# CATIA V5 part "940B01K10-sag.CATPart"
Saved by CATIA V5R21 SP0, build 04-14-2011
Part number: 940B01K10-sag
Bounding box of the stored display mesh (mm): x -49.351 to 77.949, y -15.698 to 19.302, z -6.85 to 7.15
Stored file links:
  C:\Users\ALI OZGUN\Desktop\alhan\940B01K10-sag.CATPart
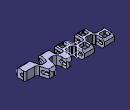
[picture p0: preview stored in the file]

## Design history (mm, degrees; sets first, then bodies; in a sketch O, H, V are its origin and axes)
Set1 "CURVE"
  DatumCurve1 to DatumCurve105
  Plane1: stored without definition
Set2 "SURFACE"
  Plane2: type 1Curve, Element1 DatumCurve19
  Sketch1 on Plane2, origin (0, 0, -3.1959), H (1, 0, 0), V (0, -1, 0)
    line L1 (49.4472, 15.9983) -> (32.7694, 15.9983)
    line L2 (48.5473, -19.0017) -> (65.7661, -19.0017)
    line L3 (-61.2339, -0.5841) -> (-61.2339, 15.0809)
    line L4 (65.7661, -19.0017) -> (65.7661, 3.0782)
    point P1 (65.7661, -19.0017)
    line L5 (49.4472, 15.9983) -> (49.0081, 3.1001)
    line L6 (49.0081, 3.1001) -> (53.2715, -2.5577)
    line L7 (53.2715, -2.5577) -> (61.843, -2.5577)
    point P2 (49.0081, 3.1001)
    point P3 (53.2715, -2.5577)
    point P4 (49.4472, 15.9983)
    line L8 (61.843, -2.5577) -> (65.7661, 3.0782)
    point P5 (61.843, -2.5577)
    point P6 (65.7661, 3.0782)
    reference intersected line E1 through (0, 0) direction (0, 1) from yz-plane
    reference intersected line E2 through (0, 0) direction (0, 1) from yz-plane
    construction line L9 (41.1083, 0) -> (41.1083, 12.9106)
    construction line L10 (41.1083, 12.9106) -> (46.3559, 12.9106)
    construction line L11 (46.3559, 12.9106) -> (46.3559, 3.0133)
    construction line L12 (46.3559, 3.0133) -> (41.1083, 3.0133)
    point P7 (46.3559, 12.9106)
    point P8 (46.3559, 3.0133)
    point P9 (41.1083, 12.9106)
    point P10 (41.1083, 3.0133)
    line L13 (41.1083, 0) -> (50.5276, 0)
    line L14 (48.5473, -19.0017) -> (50.5276, 0)
    point P11 (50.5276, 0)
    point P12 (41.1083, 0)
    point P13 (48.5473, -19.0017)
    point P14 (35.8607, 12.9106)
    point P15 (41.1083, 12.9106)
    construction line L15 (41.1083, 12.9106) -> (35.8607, 12.9106)
    point P16 (35.8607, 3.0133)
    construction line L16 (35.8607, 12.9106) -> (35.8607, 3.0133)
    point P17 (41.1083, 3.0133)
    construction line L17 (35.8607, 3.0133) -> (41.1083, 3.0133)
    point P18 (31.6891, 0)
    point P19 (41.1083, 0)
    line L18 (41.1083, 0) -> (31.6891, 0)
    point P20 (33.6694, -19.0017)
    line L19 (33.6694, -19.0017) -> (31.6891, 0)
    point P21 (16.4506, -19.0017)
    line L20 (33.6694, -19.0017) -> (16.4506, -19.0017)
    point P22 (16.4506, 3.0782)
    line L21 (16.4506, -19.0017) -> (16.4506, 0)
    point P23 (20.3736, -2.5577)
    line L22 (20.3736, -2.5577) -> (16.5464, 2.9405)
    point P24 (28.9451, -2.5577)
    line L23 (28.9451, -2.5577) -> (20.3736, -2.5577)
    point P25 (33.2086, 3.1001)
    line L24 (33.2086, 3.1001) -> (28.9451, -2.5577)
    point P26 (32.7694, 15.9983)
    line L25 (32.7694, 15.9983) -> (33.2086, 3.1001)
    axis line L26 (24.8802, -15.8106) -> (24.8802, 20.8842)
    line L27 (16.991, 15.9983) -> (16.5464, 2.9405)
    point P29 (13.8998, 3.0133)
    point P30 (13.8998, 12.9106)
    construction line L28 (13.8998, 12.9106) -> (13.8998, 3.0133)
    point P31 (8.6521, 0)
    line L29 (8.6521, 0) -> (16.4506, 0)
    point P32 (8.6521, 0)
    line L30 (8.6521, 0) -> (-0.2618, 0)
    point P33 (3.4045, 3.0133)
    point P34 (3.4045, 12.9106)
    construction line L31 (3.4045, 12.9106) -> (3.4045, 3.0133)
    point P35 (8.6521, 3.0133)
    construction line L32 (3.4045, 3.0133) -> (8.6521, 3.0133)
    point P36 (8.6521, 3.0133)
    construction line L33 (13.8998, 3.0133) -> (8.6521, 3.0133)
    point P37 (8.6521, 12.9106)
    construction line L34 (8.6521, 12.9106) -> (3.4045, 12.9106)
    point P38 (8.6521, 12.9106)
    construction line L35 (8.6521, 12.9106) -> (13.8998, 12.9106)
    point P39 (0.3133, 15.9983)
    line L36 (0.3133, 15.9983) -> (0.7524, 3.1001)
    line L37 (0.7524, 3.1001) -> (-3.8134, -2.9589)
    line L38 (16.991, 15.9983) -> (0.3133, 15.9983)
    line L39 (-0.2618, 0) -> (0.5916, -19.0017)
    line L40 (-12.1477, -5.1469) -> (-12.4932, -19.0017)
    line L41 (-3.8134, -2.9589) -> (-12.4906, -2.9589)
    line L42 (-12.4906, -2.9589) -> (-12.6654, 12.1222)
    line L43 (-29.6656, -3.0126) -> (-25.0164, 15.9983)
    line L44 (-39.0662, -3.1542) -> (-29.6656, -3.0126)
    line L45 (-44.327, 15.3928) -> (-39.0662, -3.1542)
    line L46 (-43.9186, 0.391) -> (-38.7475, -19.0017)
    line L47 (-43.9186, 0.391) -> (-61.2339, -0.5841)
    line L48 (-61.2339, 15.0809) -> (-44.327, 15.3928)
    line L49 (-16.4275, 15.9983) -> (-25.0164, 15.9983)
    line L50 (-16.4275, 15.9983) -> (-12.6654, 12.1222)
    line L51 (-24.9197, 0.2086) -> (-29.3974, -19.0017)
    line L52 (-24.9197, 0.2086) -> (-16.3942, 0.2086)
    line L53 (-16.3942, 0.2086) -> (-12.1477, -5.1469)
    line L54 (-29.3974, -19.0017) -> (-38.7475, -19.0017)
    line L55 (0.5916, -19.0017) -> (-12.4932, -19.0017)
    distance L2 L1 = 35
    distance L3 L4 = 127
    angle E1 L5 = 1.95
    angle E2 L6 = 37
    horizontal: L1 H, L2 H, L7 H, L10 H, L12 H, L13 H, L38 H, L41 H, L49 H, L52 H
    fix: L1, L9
    vertical: L3 V, L4 V, L9 V, L11 V, L26 V
    coincidence: P10 L9, L1 L38, P22 L22, P22 L21, L38 L49, L20 L54, L20 L55
    symmetry: P7 P14 L9, P9 P15 L9, L10 L15 L9, P8 P16 L9, L11 L16 L9, P10 P17 L9, L12 L17 L9, P11 P18 L9, P12 P19 L9, L13 L18 L9, P13 P20 L9, L14 L19 L9, P1 P21 L9, L2 L20 L9, P6 P22 L9, L4 L21 L9, P5 P23 L9, L8 L22 L9, P3 P24 L9, L7 L23 L9, P2 P25 L9, L6 L24 L9, P4 P26 L9, L5 L25 L9, L25 L27 L26, P16 P29 L26, P14 P30 L26, L16 L28 L26, P19 P31 L26, L18 L29 L26, P12 P32 L26, L13 L30 L26, P8 P33 L26, P7 P34 L26, L11 L31 L26, P10 P35 L26, L12 L32 L26, P17 P36 L26, L17 L33 L26, P9 P37 L26, L10 L34 L26, P15 P38 L26, L15 L35 L26, P4 P39 L26, L5 L36 L26, L6 L37 L26
  Sweep1: type Segment, GuideCrv Sketch1, Length1 4, Length2 5, Angle -1, DraftDirection (0, 0, 1)
  Sketch2 on yz-plane, origin (0, 0, 0), H (0, 1, 0), V (0, 0, 1)
    line L1 (-24.9191, -6.9968) -> (50.389, -6.9968)
    horizontal: L1 H
  Extrude1: Element1 Sketch2, Lim1 80, Lim2 80
  Trim1: Trimmed (Sweep1; Extrude1)
  Sketch3 on yz-plane, origin (0, 0, 0), H (0, 1, 0), V (0, 0, 1)
    line L1 (-48.3055, 0) -> (52.6647, 0)
    horizontal: L1 H
    coincidence: O L1
  Extrude2: Element1 Sketch3, Lim1 80, Lim2 80
  Trim2: Trimmed (Trim1; Extrude2)
  Extrude3: Element1 Sketch7, Lim1 10, Lim2 10
  Translate1: ToTransfor Extrude3, Direction (1, 0, 0), Length 32.6
  Extrude4: Element1 Sketch8, Lim1 10, Lim2 10
  Translate2: ToTransfor Extrude4, Direction (1, 0, 0), Length 32.8
  Sweep2: type Segment, GuideCrv Sketch11, Length1 10, Length2 5, Angle -1, DraftDirection (0, 0, 1)
  Translate3: ToTransfor Sweep2, Direction (1, 0, 0), Length -32.8
  Sketch4 on face of CloseSurface1, origin (0, 0, 0), H (1, 0, 0), V (0, 1, 0)
    line L1 (-3.8486, 19.8441) -> (1.0015, 13.5162)
  Sweep3: type Segment, GuideCrv Sketch4, Length1 10, Length2 5, Angle 1, DraftDirection (0, 0, 1)
  Plane3: type 1Curve, Element1 DatumCurve99
  Sketch5 on Plane3, origin (0, 0, -5.2979), H (1, 0, 0), V (0, -1, 0)
    line L1 (-37.6706, -7.3878) -> (-35.3775, -14.835)
    line L2 (-32.6098, -14.835) -> (-30.9175, -7.3878)
    offset line E2 (-36.4878, -14.835) -> (-31.7318, -14.835) from edge [face of Mirror1 | face of CloseSurface1]
    offset line E3 (-35.3775, -14.835) -> (-32.6098, -14.835) from edge [face of Mirror1 | face of CloseSurface1]
    line L3 (-37.6706, -7.3878) -> (-30.9175, -7.3878)
    point P5 (-36.4878, -7.3878)
    point P6 (-31.7318, -7.3878)
    construction line L4 (-36.4878, -14.835) -> (-36.4878, -7.3878)
    construction line L5 (-31.7318, -14.835) -> (-31.7318, -7.3878)
    distance E2 L3 = 7.4472
    perpendicularity: L4 E2, L4 L3, L5 E2, L5 L3
    coincidence: P5 L3, P6 L3
  Sweep4: type Segment, GuideCrv Sketch5, Length1 5, Length2 5, Angle -1, DraftDirection (0, 0, 1)
  Sketch6 on yz-plane, origin (0, 0, 0), H (0, 1, 0), V (0, 0, 1)
    line L1 (-47.946, -0.4507) -> (26.6531, -0.4507)
    horizontal: L1 H
  Extrude5: Element1 Sketch6, Lim1 100, Lim2 100
  Trim3: Trimmed (Sweep4; Extrude5)
  Sweep5: type Segment, GuideCrv Sketch12, Length1 5, Length2 5, Angle -1, DraftDirection (0, 0, 1)
  Trim4: Trimmed (Extrude5; Sweep5)
  MultiExtract1: ListOfMultiExtractConstraints (MultiExtractConstraint face of Split9; MultiExtractConstraint face of Fillet45; MultiExtractConstraint face of Split9; MultiExtractConstraint face of Fillet47; MultiExtractConstraint face of Split9; MultiExtractConstraint face of Split9; MultiExtractConstraint face of Fillet49; MultiExtractConstraint face of Fillet48; MultiExtractConstraint face of Fillet46; MultiExtractConstraint face of Split9)
  Extrapol1: ToExtrapol edge of MultiExtract1, Support MultiExtract1, Length 10
  Extrapol2: ToExtrapol edge [end face of Pocket4 | face of Pocket5 from Sketch15.E2], Support face of Pocket5 from Sketch15.E2, Length 10
  Trim5: Trimmed (Extrapol1; Extrapol2)
  Extrapol3: ToExtrapol edge of MultiExtract1, Support Trim5, Length 1
  Extrapol4: ToExtrapol edge [face of Pocket4 from Sketch14.L2 | face of CloseSurface1], Support face of Pocket4 from Sketch14.L2, Length 5
  Extrapol5: ToExtrapol edge [face of Pocket4 from Sketch14.L1 | face of Mirror1], Support face of Pocket4 from Sketch14.L1, Length 5
  Extrapol6: ToExtrapol edge [face of Mirror1 | face of Pocket4 from Sketch14.L4], Support face of Pocket4 from Sketch14.L4, Length 5
  Trim6: Trimmed (Extrapol6; Extrapol5; Extrapol4)
  Extrapol7: ToExtrapol edge [face of CloseSurface1 | face of Split10], Support face of Split10, Length 5
  Trim7: Trimmed (Extrapol7; Trim6)
  Extrapol8: ToExtrapol edge [face of CloseSurface1 | face of Pocket4 from Sketch14.L3], Support face of Pocket4 from Sketch14.L3, Length 5
  Trim8: Trimmed (Extrapol8; Trim7)
Set3
  CLDGeom1 "4_1.1"
  Plane4: type Offset, RefPlane yz-plane, Offset -63
Body1 (main body)
  CloseSurface1: CloseElement Trim2
  Sketch7 on face of CloseSurface1, origin (0, 0, -6.9968), H (1, 0, 0), V (0, -1, 0)
    line L1 (3.5232, 12.867) -> (13.7904, 12.867)
    line L2 (13.7904, 12.867) -> (13.7904, 3.1238)
    line L3 (13.7904, 3.1238) -> (3.5232, 3.1238)
    line L4 (3.5232, 3.1238) -> (3.5232, 12.867)
    horizontal: L1 H, L3 H
    vertical: L2 V, L4 V
    fix: L4, L1
  Split1: SplitPlane Extrude3
  Split2: SplitPlane Translate1
  Sketch8 on face of CloseSurface1, origin (0, 0, -6.9968), H (1, 0, 0), V (0, -1, 0)
    line L1 (19.6709, -6.2611) -> (30.062, -6.2611)
    line L2 (30.062, -6.2611) -> (30.062, -15.6449)
    line L3 (30.062, -15.6449) -> (19.6709, -15.6449)
    line L4 (19.6709, -15.6449) -> (19.6709, -6.2611)
    horizontal: L1 H, L3 H
    vertical: L2 V, L4 V
    fix: L1, L4, L2
  Split3: SplitPlane Translate2
  Split4: SplitPlane Extrude4
  Sketch9 on face of CloseSurface1, origin (0, 0, -6.9968), H (1, 0, 0), V (0, -1, 0)
    line L1 (-8.0734, -6.1533) -> (-4.0044, -6.1533)
    line L2 (-4.0044, -6.1533) -> (-4.0044, -14.5157)
    line L3 (-4.0044, -14.5157) -> (-8.0734, -14.5157)
    line L4 (-8.0734, -14.5157) -> (-8.0734, -6.1533)
    horizontal: L1 H, L3 H
    vertical: L2 V, L4 V
  Pocket1: profile Sketch9, direction (0, 0, 1), length 20
  Sketch10 on face of CloseSurface1, origin (0, 0, -6.9968), H (1, 0, 0), V (0, -1, 0)
    line L1 (-16.7652, 4.7837) -> (-23.421, 4.7837)
    line L2 (-21.5701, 11.8402) -> (-16.7652, 11.8402)
    line L3 (-16.7652, 11.8402) -> (-16.7652, 4.7837)
    line L4 (-23.421, 4.7837) -> (-21.5701, 11.8402)
    horizontal: L1 H, L2 H
    vertical: L3 V
  Pocket2: profile Sketch10, direction (0, 0, 1), length 20
  Draft1: Angle 1, Neutral face of CloseSurface1, PullDir face of CloseSurface1, SupportToDraft (face of Split3; face of Split3; face of Split3; face of Split3; face of Split2; face of Split2; face of Split2; face of Split2; face of Split4; face of Split4; face of Split4; face of Split4; face of Split1; face of Split1; face of Split1; face of Split1; face of Pocket1 from Sketch9.L2; face of Pocket1 from Sketch9.L4; face of Pocket1 from Sketch9.L3; face of Pocket1 from Sketch9.L1; face of Pocket2 from Sketch10.L1; face of Pocket2 from Sketch10.L3; face of Pocket2 from Sketch10.L2; face of Pocket2 from Sketch10.L4)
  Chamfer1: length 2.85, angle 44, on edge [face of CloseSurface1 | face of CloseSurface1] (x8)
  Thickness1: Face (face of Chamfer1; face of Chamfer1; face of Chamfer1; face of Chamfer1), Thickness 0.15
  Thickness2: Face (face of Chamfer1; face of Chamfer1; face of Chamfer1; face of Chamfer1), Thickness 0.4
  Sketch11 on face of CloseSurface1, origin (0, 0, 0), H (1, 0, 0), V (0, 1, 0)
    line L1 (57.6565, 24.4948) -> (67.109, 12.822)
    line L2 (46.3763, 10.5649) -> (57.6565, 24.4948)
    angle V L2 = 39
    angle L1 V = 39
  Split5: SplitPlane Sweep2
  Split6: SplitPlane Translate3
  Split7: SplitPlane Sweep3
  Thickness3: Face face of Split7, Thickness -0.1
  Fillet1: radius 0.75, on edge [face of CloseSurface1 | face of CloseSurface1]
  Fillet2: radius 4, on edge [face of Split6 | face of CloseSurface1]; edge [face of Split5 | face of CloseSurface1]
  Fillet3: radius 4.5, on edge [face of Split6 | face of CloseSurface1]; edge [face of Split5 | face of CloseSurface1]
  Fillet4: radius 4.5, on edge [face of Split6 | face of CloseSurface1]; edge [face of Split5 | face of CloseSurface1]
  Fillet5: radius 4.5, on edge [face of CloseSurface1 | face of Split5]; edge [face of CloseSurface1 | face of Split6]
  Fillet6: radius 3.5, on edge [face of CloseSurface1 | face of CloseSurface1] (x4)
  Fillet7: radius 3, on edge [face of Split7 | face of CloseSurface1]
  Fillet8: radius 3, on edge [face of Split7 | face of CloseSurface1]
  Fillet9: radius 4, on edge [face of CloseSurface1 | face of CloseSurface1]
  Fillet10: radius 3, on edge [face of CloseSurface1 | face of CloseSurface1]
  Fillet11: radius 3, on edge [face of CloseSurface1 | face of CloseSurface1]
  Fillet12: radius 3, on edge [face of CloseSurface1 | face of CloseSurface1]
  Fillet13: radius 3, on edge [face of CloseSurface1 | face of CloseSurface1]
  Fillet14: radius 3, on edge [face of CloseSurface1 | face of CloseSurface1]
  Fillet15: radius 3, on edge [face of CloseSurface1 | face of CloseSurface1]
  Fillet16: radius 3, on edge [face of CloseSurface1 | face of CloseSurface1]
  Fillet17: radius 3, on edge [face of CloseSurface1 | face of CloseSurface1] (x2)
  Fillet18: radius 0.75, on edge [face of CloseSurface1 | face of CloseSurface1]
  Fillet19: radius 0.75, on edge [face of CloseSurface1 | face of CloseSurface1]
  Fillet20: radius 3, on edge [face of CloseSurface1 | face of CloseSurface1] (x4)
  Fillet21: radius 0.75, on edge [face of CloseSurface1 | face of CloseSurface1] (x2)
  Fillet22: radius 3, on edge [face of CloseSurface1 | face of CloseSurface1] (x2)
  Fillet23: radius 4, on edge [face of CloseSurface1 | face of CloseSurface1]
  Fillet24: radius 3, on edge [face of CloseSurface1 | face of CloseSurface1]
  Fillet25: radius 1.5, on edge [face of CloseSurface1 | face of CloseSurface1] (x2)
  Fillet26: radius 3, on edge [face of CloseSurface1 | face of CloseSurface1] (x2)
  Fillet27: radius 3, on edge [face of CloseSurface1 | face of CloseSurface1]
  Fillet28: radius 0.5, on edge [face of CloseSurface1 | face of CloseSurface1]
  Fillet29: radius 0.5, on edge [face of CloseSurface1 | face of CloseSurface1]
  Fillet30: radius 2.75, on edge [face of Split4 | face of Split4] (x2); edge [face of Split3 | face of Split3] (x2)
  Fillet31: radius 2, on edge [face of Split4 | face of Split4] (x2); edge [face of Split3 | face of Split3] (x2)
  Fillet32: radius 2.75, on edge [face of Split2 | face of Split2] (x2)
  Fillet33: radius 2, on edge [face of Split2 | face of Split2] (x2)
  Fillet34: radius 1.5, on edge [face of Split1 | face of Split1] (x2)
  Fillet35: radius 1.75, on edge [face of Split1 | face of Split1] (x2)
  TritangentFillet1: Face1 face of Pocket1 from Sketch9.L4, Face2 face of Pocket1 from Sketch9.L2, RemoveFace face of Pocket1 from Sketch9.L1
  TritangentFillet2: Face1 face of Pocket1 from Sketch9.L4, Face2 face of Pocket1 from Sketch9.L2, RemoveFace face of Pocket1 from Sketch9.L3
  Fillet36: radius 1.75, on edge [face of Pocket2 from Sketch10.L2 | face of Pocket2 from Sketch10.L3]
  Fillet37: radius 1, on edge [face of Pocket2 from Sketch10.L4 | face of Pocket2 from Sketch10.L2]
  Fillet38: radius 1.5, on edge [face of Pocket2 from Sketch10.L4 | face of Pocket2 from Sketch10.L1]
  Fillet39: radius 1.75, on edge [face of Pocket2 from Sketch10.L3 | face of Pocket2 from Sketch10.L1]
  Fillet40: radius 0.5, on edge [face of CloseSurface1 | face of CloseSurface1] (x8)
  Fillet41: radius 0.5, on edge [face of Chamfer1 | face of CloseSurface1]
  Fillet42: radius 0.5, on edge [face of Chamfer1 | face of CloseSurface1]
  Fillet43: radius 0.5, on edge [face of Chamfer1 | face of CloseSurface1] (x2)
  Fillet44: radius 0.5, on edge [face of Chamfer1 | face of CloseSurface1] (x4)
  Thickness4: Face face of CloseSurface1, Thickness 0.15
  Mirror1: of the body so far, about face of CloseSurface1
  Split8: SplitPlane Trim3
  Sketch12 on Plane3, origin (0, 0, -5.2979), H (1, 0, 0), V (0, -1, 0)
    line L1 (-57.1409, 11.1692) -> (-47.5031, 11.1692)
    line L2 (-46.3543, 7.2877) -> (-46.3543, 4.9902)
    line L3 (-46.3543, 4.9902) -> (-57.1409, 4.9902)
    line L4 (-57.1409, 4.9902) -> (-57.1409, 11.1692)
    line L5 (-47.5031, 11.1692) -> (-46.3543, 7.2877)
    horizontal: L1 H, L3 H
    vertical: L2 V, L4 V
  Split9: SplitPlane Trim4
  Fillet45: radius 2, on edge [face of Split9 | face of Split9]
  Fillet46: radius 2, on edge [face of Split9 | face of Split9]
  Fillet47: radius 1.9, on edge [face of Split9 | face of Split9]
  Fillet48: radius 2, on edge [face of Split9 | face of Split9]
  Fillet49: radius 2, on edge [face of Split9 | face of Split9]
  Fillet50: radius 2, on edge [face of Split8 | face of Split8]
  Fillet51: radius 2, on edge [face of Split8 | face of Split8]
  Fillet52: radius 1.5, on edge [face of Split8 | face of Split8] (x2)
  Sketch13 on yz-plane, origin (0, 0, 0), H (0, 1, 0), V (0, 0, 1)
    line L1 (4.7142, -2.0988) -> (16.0181, -2.0988)
    line L2 (16.0181, -2.0988) -> (16.0181, 2.7411)
    line L3 (16.0181, 2.7411) -> (4.7142, 2.7411)
    line L4 (4.7142, 2.7411) -> (4.7142, -2.0988)
    horizontal: L1 H, L3 H
    vertical: L2 V, L4 V
  Pocket3: profile Sketch13, direction (-1, 0, 0), length 111, opposite side length 100
  Sketch14 on yz-plane, origin (0, 0, 0), H (0, 1, 0), V (0, 0, 1)
    line L1 (-13.6557, 2.8812) -> (-2.4057, 2.8812)
    line L2 (-2.4057, 2.8812) -> (-2.4057, -2.1188)
    line L3 (-2.4057, -2.1188) -> (-13.6557, -2.1188)
    line L4 (-13.6557, -2.1188) -> (-13.6557, 2.8812)
    distance L1 L3 = 5
    distance L4 L2 = 11.25
    horizontal: L1 H, L3 H
    vertical: L2 V, L4 V
    fix: L1
  Pocket4: profile Sketch14, direction (-1, 0, 0), length 55, opposite side length 100
  Sketch15 on Plane4, origin (-63, 0, 0), H (0, 1, 0), V (0, 0, 1)
    projected line E1 (16.0181, 2.7411) -> (4.7142, 2.7411) from edge [face of Pocket3 from Sketch13.L3 | face of Mirror1]
    projected line E2 (2.9895, 2.7411) -> (-6.2509, 2.7411) from edge [face of Pocket3 from Sketch13.L3 | face of Mirror1]
    projected line E3 (16.0181, -2.0988) -> (4.7142, -2.0988) from edge [face of CloseSurface1 | face of Pocket3 from Sketch13.L1]
    projected line E4 (2.9895, -2.0988) -> (-6.2509, -2.0988) from edge [face of CloseSurface1 | face of Pocket3 from Sketch13.L1]
    line L1 (-6.2509, -2.0988) -> (-6.2509, 2.7411)
    line L2 (2.9895, 2.7411) -> (2.9895, -2.0988)
    vertical: L1 V, L2 V
  Pocket5: profile Sketch15, direction (1, 0, 0), length 11
  Split10: SplitPlane Extrapol3
  Split11: SplitPlane Trim8
  Align1: SewingRemoveFace face of Split11, SplitPlane face of Split10
  Thickness5: Face (face of Split11; face of Pocket5 from Sketch15.E4), Thickness 0.15
  Align2: SewingRemoveFace face of Pocket5 from Sketch15.E4, SplitPlane face of Split11
  RemoveFace1: RemoveFaces (face of Pocket4 from Sketch14.L3; face of Pocket4 from Sketch14.L1; face of Pocket4 from Sketch14.L4; face of Pocket4 from Sketch14.L2; face of Pocket4 from Sketch14.L2; face of Pocket4 from Sketch14.L1; face of Pocket4 from Sketch14.L3; face of Pocket4 from Sketch14.L4; face of Pocket4 from Sketch14.L4; face of Pocket4 from Sketch14.L1; face of Pocket4 from Sketch14.L2; face of Pocket4 from Sketch14.L3)
  RemoveFace2: RemoveFaces (face of Pocket3 from Sketch13.L3; face of Pocket3 from Sketch13.L4; face of Pocket3 from Sketch13.L1; face of Pocket3 from Sketch13.L2; face of Pocket3 from Sketch13.L4; face of Pocket3 from Sketch13.L3; face of Pocket3 from Sketch13.L1; face of Pocket3 from Sketch13.L2; face of Pocket3 from Sketch13.L3; face of Pocket3 from Sketch13.L4; face of Pocket3 from Sketch13.L2; face of Pocket3 from Sketch13.L1)
  Draft2: Angle 0, Neutral xy-plane, PullDir xy-plane, SupportToDraft (face of Mirror1; face of Split1; face of Mirror1; face of Split2; face of Mirror1; face of Fillet31; face of Mirror1; face of Fillet31; face of Mirror1; face of Fillet36)
  RemoveFace3: RemoveFaces (face of Split10; face of Split11; face of Split10; face of Split10; face of Split10; face of Split10; face of Split10; face of Split10; face of Split10; face of Split10; face of Split10; end face of Pocket5; face of Split11; face of Split11; face of Pocket5 from Sketch15.L1; face of Split11)
  Sketch16 on face of CloseSurface1, origin (0, 0, -6.9968), H (1, 0, 0), V (0, -1, 0)
    projected curve E1 from edge [face of Split11 | face of Split10]
    projected line E2 (-55.083, 5.0483) -> (-48.3121, 5.0483) from edge [face of Split10 | face of Split11]
    projected curve E3 from edge [face of Split11 | face of Split10]
    projected line E4 (-46.4946, 7.5571) -> (-47.1226, 9.6789) from edge [face of Split10 | face of Split11]
    projected arc E5 centre (-48.414, 6.9893) radius 2.0016 from (-46.4124, 6.9896) to (-46.4946, 7.5571) ccw from edge [face of Split11 | face of Split10]
    projected curve E6 from edge [face of Split11 | face of Split10]
    projected line E7 (-49.0401, 11.1111) -> (-55.083, 11.1111) from edge [face of Split10 | face of Split11]
    projected curve E8 from edge [face of Split11 | face of Split10]
    line L1 (-57.0827, 9.1114) -> (-57.0827, 7.048)
    projected line E9 (-46.4124, 6.948) -> (-46.4124, 6.9896) from edge [face of Split10 | face of Split11]
    projected line E10 (-33.4926, -7.4437) -> (-34.8869, -7.4437) from edge [face of Split8 | face of Pocket3 from Sketch13.L1]
    projected curve E11 from edge [face of Pocket3 from Sketch13.L1 | face of Fillet51]
    projected line E12 (-32.3891, -13.6117) -> (-31.5426, -9.8864) from edge [face of Split8 | face of Pocket3 from Sketch13.L1]
    projected curve E13 from edge [face of Pocket3 from Sketch13.L1 | face of Fillet52]
    projected curve E14 from edge [face of Fillet52 | face of Pocket3 from Sketch13.L1]
    projected line E15 (-34.2288, -14.7792) -> (-33.8515, -14.7792) from edge [face of Split8 | face of Pocket3 from Sketch13.L1]
    projected line E16 (-36.798, -10.0318) -> (-35.6622, -13.7207) from edge [face of Split8 | face of Pocket3 from Sketch13.L1]
    projected curve E17 from edge [face of Fillet50 | face of Pocket3 from Sketch13.L1]
    vertical: L1 V
  Draft3: Angle 0, Neutral face of Pocket3 from Sketch13.L1, PullDir face of Pocket3 from Sketch13.L1, SupportToDraft face of Fillet52
  RemoveFace4: RemoveFaces (face of Pocket3 from Sketch13.L1; face of Pocket3 from Sketch13.L4; face of Pocket3 from Sketch13.L3; face of Pocket3 from Sketch13.L2; face of Split8; face of Fillet52; face of Split8; face of Fillet52; face of Split8; face of Fillet50; face of Split8; face of Fillet51)
  Pocket6: profile Sketch16, direction (0, 0, 1), up to xy-plane
  Sketch17 on yz-plane, origin (0, 0, 0), H (0, 1, 0), V (0, 0, 1)
    construction line L1 (-11.1983, 0.15) -> (-5.1983, 0.15)
    point P1 (-11.1983, 0.15)
    line L2 (-11.1983, 2.65) -> (-5.1983, 2.65)
    line L3 (-5.1983, -2.35) -> (-11.1983, -2.35)
    arc A1 centre (-5.1983, 0.15) radius 2.5 from (-5.1983, 2.65) to (-5.1983, -2.35) cw
    arc A2 centre (-11.1983, 0.15) radius 2.5 from (-11.1983, -2.35) to (-11.1983, 2.65) cw
    point P3 (-11.1983, 2.65)
    point P4 (-5.1983, 2.65)
    point P5 (-5.1983, -2.35)
    point P6 (-11.1983, -2.35)
    reference projected line E1 (12.9961, 0.15) -> (-0.8745, 0.15) from edge [face of Mirror1 | face of CloseSurface1]
    construction line L4 (19.0601, 0.15) -> (-16.0567, 0.15)
    axis line L5 (1.5017, 0.15) -> (1.5017, 16.5006)
    point P7 (1.5017, 0.15)
    construction line L6 (14.2017, 0.15) -> (8.2017, 0.15)
    point P11 (14.2017, 2.65)
    point P12 (8.2017, 2.65)
    point P13 (8.2017, -2.35)
    point P14 (14.2017, -2.35)
    line L7 (14.2017, 2.65) -> (8.2017, 2.65)
    line L8 (8.2017, -2.35) -> (14.2017, -2.35)
    arc A3 centre (8.2017, 0.15) radius 2.5 from (8.2017, 2.65) to (8.2017, -2.35) ccw
    arc A4 centre (14.2017, 0.15) radius 2.5 from (14.2017, -2.35) to (14.2017, 2.65) ccw
    distance L1 L2 = 2.5
    distance P1 L5 = 12.7
    length L1 = 6
    horizontal: L1 H, L4 H
    tangency: A1 L2, A2 L2, A1 L3, A2 L3
    coincidence: L1 E1
    midpoint: P7 L4
    vertical: L5 V
    symmetry: L1 L6 L5, P3 P11 L5, P4 P12 L5, P5 P13 L5, P6 P14 L5, L2 L7 L5, L3 L8 L5, A1 A3 L5, A2 A4 L5
  Sketch18 on xy-plane, origin (0, 0, 0), H (1, 0, 0), V (0, 1, 0)
    line L1 (-59.6762, 27.1723) -> (64.7084, 27.1723)
    line L2 (64.7084, 27.1723) -> (64.7084, -29.9789)
    line L3 (64.7084, -29.9789) -> (-59.6762, -29.9789)
    line L4 (-59.6762, -29.9789) -> (-59.6762, 27.1723)
    reference projected line E1 through (65.2084, 0) direction (0, -1) from axis of face of Mirror1
    reference projected line E2 (-60.6762, -12.5832) -> (-60.6762, -0.0059) from edge [face of Mirror1 | face of Mirror1]
    distance L2 E1 = 0.5
    distance L4 E2 = 1
    horizontal: L1 H, L3 H
    vertical: L2 V, L4 V
  Pocket7: profile Sketch18, direction (0, 0, -1), length 94, mirrored extent, outer side
  Thickness6: Face face of Pocket7 from Sketch18.L4, Thickness 2
  Thickness7: Face face of Pocket7 from Sketch18.L4, Thickness 1.115
  Pocket8: profile Sketch17, direction (-1, 0, 0), length 94, mirrored extent
  Sketch19 on yz-plane, origin (0, 0, 0), H (0, 1, 0), V (0, 0, 1)
    arc A1 centre (-5.1983, 0.15) radius 2.5 from (-5.1983, 2.65) to (-5.1983, -2.35) ccw
    point P10 (-5.1983, -2.35)
    line L1 (-11.1983, 2.65) -> (-5.1983, 2.65)
    arc A2 centre (-11.1982, 0.15) radius 2.5 from (-11.1983, 2.65) to (-13.6983, 0.15) ccw
    arc A3 centre (-11.1982, 0.15) radius 2.5 from (-13.6983, 0.15) to (-11.1983, -2.35) ccw
    line L2 (-5.1983, -2.35) -> (-11.1983, -2.35)
    construction arc A4 centre (-5.1983, 0.15) radius 2.5 from (-2.6983, 0.15) to (-5.1983, 2.65) ccw
    coincidence: A1 A4, L2 P10
  Pad1: profile Sketch19, direction (-1, 0, 0), length 94, opposite side up to face of Pocket6 from Sketch16.L1
  Split12: SplitPlane face of Pocket7 from Sketch18.L4
Body2
  Solid1: linked copy from another document
  Translate4: ToTransfor Solid1, Direction zx-plane, Length -19
Body3
  Solid2: solid without history
  Translate5: Direction edge [face of Solid3 | face of Solid3], ToTransfor Solid2, Length 15
Body4
  Solid3: solid without history
  Split13: SplitPlane face of Solid3
  Body5
    Sketch20 on face of Solid3, origin (0, 0, -6.85), H (1, 0, 0), V (0, -1, 0)
      line L1 (-77.9488, 12.497) -> (-77.9488, 2.8937)
      line L2 (-75.055, 0) -> (-62.8479, 0)
      line L3 (-58.0492, -3.5955) -> (-54.3874, -16.1072)
      line L4 (-50.1239, -19.3017) -> (-48.9356, -19.3017)
      line L5 (-43.8676, -15.3198) -> (-40.7729, -2.6121)
      point P1 (-40.1368, 0)
      line L6 (-37.4484, 0) -> (-33.9228, 0)
      line L7 (-28.7341, -2.6853) -> (-28.7254, -2.6976)
      line L8 (-26.6939, -9.0873) -> (-26.6939, -16.7891)
      point P2 (-26.6939, -19.3017)
      line L9 (-24.1812, -19.3017) -> (-23.1488, -19.3017)
      line L10 (-19.4647, -17.5249) -> (-18.7392, -16.613)
      line L11 (-16.7488, -10.9137) -> (-16.7488, -5.4517)
      line L12 (-18.0368, -2.7398) -> (-21.509, -2.7398)
      line L13 (-27.885, 3.6363) -> (-27.885, 12.2509)
      line L14 (-27.885, 12.2509) -> (-31.292, 15.6983)
      line L15 (-31.292, 15.6983) -> (-40.4229, 15.6983)
      line L16 (-40.4229, 15.6983) -> (-44.4156, -0.6971)
      line L17 (-47.975, -3.4937) -> (-52.1939, -3.4937)
      line L18 (-55.7282, -0.8455) -> (-59.3074, 11.3836)
      line L19 (-65.0658, 15.6983) -> (-74.7475, 15.6983)
      projected line E1 (-16.6488, -5.3517) -> (-13.9346, -2.6375) from edge [face of Solid3 | face of Solid3]
      projected line E2 (-16.7488, -5.4517) -> (-13.9346, -2.6375) from edge [face of Solid3 | face of Solid3]
      projected line E3 (-18.1594, -2.8624) -> (-16.5488, -1.2517) from edge [face of Solid3 | face of Solid3]
      projected line E4 (-18.0368, -2.7398) -> (-16.5488, -1.2517) from edge [face of Solid3 | face of Solid3]
      line L20 (-13.9346, -2.6375) -> (-16.5488, -1.2517)
      arc A1 centre (-21.509, 3.6363) radius 6.376 from (-21.509, -2.7398) to (-27.885, 3.6363) cw
      arc A2 centre (-37.7581, -9.0873) radius 11.0643 from (-28.7254, -2.6976) to (-26.6939, -9.0873) cw
      arc A3 centre (-33.9228, -6.3557) radius 6.3557 from (-33.9228, 0) to (-28.7341, -2.6853) cw
      arc A4 centre (-37.4484, -3.4217) radius 3.4217 from (-37.4484, 0) to (-40.7729, -2.6121) ccw
      arc A5 centre (-25.9033, -10.9137) radius 9.1545 from (-16.7488, -10.9137) to (-18.7392, -16.613) cw
      arc A6 centre (-23.1488, -14.5941) radius 4.7077 from (-23.1488, -19.3017) to (-19.4647, -17.5249) ccw
      arc A7 centre (-24.1812, -16.7891) radius 2.5127 from (-26.6939, -16.7891) to (-24.1812, -19.3017) ccw
      arc A8 centre (-48.9356, -14.0856) radius 5.2161 from (-48.9356, -19.3017) to (-43.8676, -15.3198) ccw
      arc A9 centre (-50.1239, -14.8594) radius 4.4424 from (-54.3874, -16.1072) to (-50.1239, -19.3017) ccw
      arc A10 centre (-62.8479, -5) radius 5 from (-62.8479, 0) to (-58.0492, -3.5955) cw
      arc A11 centre (-52.1939, 0.1889) radius 3.6826 from (-55.7282, -0.8455) to (-52.1939, -3.4937) ccw
      arc A12 centre (-47.975, 0.1697) radius 3.6634 from (-47.975, -3.4937) to (-44.4156, -0.6971) ccw
      arc A13 centre (-75.055, 2.8937) radius 2.8937 from (-77.9488, 2.8937) to (-75.055, 0) ccw
      arc A14 centre (-74.7475, 12.497) radius 3.2013 from (-77.9488, 12.497) to (-74.7475, 15.6983) cw
      arc A15 centre (-65.0658, 9.6983) radius 6 from (-65.0658, 15.6983) to (-59.3074, 11.3836) cw
      reference intersected line E5 (49.3512, -5.3517) -> (49.3512, -15.4984) from face of Solid3
      reference projected line E6 (-8.3488, 15.6983) -> (-12.6313, 15.6983) from edge [face of Solid3 | face of Solid3]
      reference projected line E7 (-0.0488, -5.3517) -> (-0.0488, -15.4984) from edge [face of Solid3 | face of Solid3]
      radius A1 = 6.376
      radius A2 = 11.0643
      radius A3 = 6.3557
      radius A4 = 3.4217
      radius A5 = 9.1545
      radius A6 = 4.7077
      radius A7 = 2.5127
      radius A8 = 5.2161
      radius A9 = 4.4424
      radius A10 = 5
      radius A11 = 3.6826
      radius A12 = 3.6634
      radius A13 = 2.8937
      radius A14 = 3.2013
      radius A15 = 6
      distance E5 L1 = 127.3
      angle L3 L5 = 30
      distance L4 L15 = 35
      distance L2 H = 0
      angle L16 L13 = 13.6866
      distance L11 E7 = 16.7
      distance L18 L3 = 3
      distance L16 L5 = 3.9924
      vertical: L1 V, L11 V, L13 V
      horizontal: L2 H, L4 H, L6 H, L9 H, L12 H, L15 H, L17 H, L19 H
      coincidence: P1 H, P2 L4, L6 P1, L5 P1, L8 P2, L9 P2, E6 L15, L19 L15
      tangency: A1 L12, A1 L13, A2 L7, A2 L8, A3 L6, A3 L7, A4 L6, A4 L5, A5 L11, A5 L10, A6 L9, A6 L10, A7 L8, A7 L9, A8 L4, A8 L5, A9 L3, A9 L4, A10 L2, A10 L3, A11 L18, A11 L17, A12 L17, A12 L16, A13 L1, A13 L2, A14 L1, A14 L19, A15 L19, A15 L18
      parallelism: L11 L8
    Pad2: profile Sketch20, direction (0, 0, 1), length 14
    Sketch21 on yz-plane, origin (0, 0, 0), H (0, 1, 0), V (0, 0, 1)
      projected line E1 (-5.1983, 2.65) -> (-11.1983, 2.65) from edge [face of Solid2 | face of Solid2]
      projected arc E2 centre (-11.1982, 0.15) radius 2.5 from (-11.1983, 2.65) to (-13.6983, 0.15) ccw from edge [face of Solid2 | face of Solid2]
      projected arc E3 centre (-11.1982, 0.15) radius 2.5 from (-13.6983, 0.15) to (-11.1983, -2.35) ccw from edge [face of Solid2 | face of Solid2]
      projected line E4 (-5.1983, -2.35) -> (-11.1983, -2.35) from edge [face of Solid2 | face of Solid2]
      projected arc E5 centre (-5.1982, 0.15) radius 2.5 from (-4.1662, -2.127) to (-2.6983, 0.15) ccw from edge [face of Solid2 | face of Solid2]
      projected arc E6 centre (-5.1983, 0.15) radius 2.5 from (-5.1983, -2.35) to (-4.1662, -2.127) ccw from edge [face of Solid2 | face of Solid2]
      projected arc E7 centre (-5.1982, 0.15) radius 2.5 from (-2.6983, 0.15) to (-4.1662, 2.427) ccw from edge [face of Solid2 | face of Solid2]
      projected arc E8 centre (-5.1983, 0.15) radius 2.5 from (-4.1662, 2.427) to (-5.1983, 2.65) ccw from edge [face of Solid2 | face of Solid2]
      projected arc E9 centre (8.2017, 0.15) radius 2.5 from (8.2017, 2.65) to (8.2017, -2.35) ccw from edge [face of Solid2 | face of Solid2]
      projected line E10 (8.2017, 2.65) -> (14.2017, 2.65) from edge [face of Solid2 | face of Solid2]
      projected arc E11 centre (14.2017, 0.15) radius 2.5 from (15.7359, 2.1239) to (14.2017, 2.65) ccw from edge [face of Solid2 | face of Solid2]
      projected arc E12 centre (14.2018, 0.15) radius 2.5 from (16.7017, 0.15) to (15.7359, 2.1239) ccw from edge [face of Solid2 | face of Solid2]
      projected arc E13 centre (14.2018, 0.15) radius 2.5 from (15.7359, -1.8239) to (16.7017, 0.15) ccw from edge [face of Solid2 | face of Solid2]
      projected arc E14 centre (14.2017, 0.15) radius 2.5 from (14.2017, -2.35) to (15.7359, -1.8239) ccw from edge [face of Solid2 | face of Solid2]
      projected line E15 (14.2017, -2.35) -> (8.2017, -2.35) from edge [face of Solid2 | face of Solid2]
    Pocket9: profile Sketch21, direction (-1, 0, 0), length 129
    Sketch22 on start face of Pad2, origin (0, 0, -6.85), H (1, 0, 0), V (0, -1, 0)
      projected line E1 (-23.0734, -12.4815) -> (-23.0734, -8.1875) from edge [face of Solid2 | face of Solid2]
      projected arc E2 centre (-21.0389, -8.1878) radius 2.0345 from (-19.0043, -8.1875) to (-23.0734, -8.1875) ccw from edge [face of Solid2 | face of Solid2]
      projected line E3 (-19.0044, -8.1875) -> (-19.0044, -12.4815) from edge [face of Solid2 | face of Solid2]
      projected arc E4 centre (-21.0389, -12.4811) radius 2.0345 from (-23.0734, -12.4815) to (-19.0044, -12.4815) ccw from edge [face of Solid2 | face of Solid2]
      projected line E5 (-31.8873, 9.9683) -> (-31.8873, 6.6556) from edge [face of Solid2 | face of Solid2]
      projected arc E6 centre (-33.637, 9.9684) radius 1.7496 from (-31.8873, 9.9683) to (-33.6371, 11.718) ccw from edge [face of Solid2 | face of Solid2]
      projected line E7 (-35.7044, 11.718) -> (-33.6371, 11.718) from edge [face of Solid2 | face of Solid2]
      projected arc E8 centre (-35.7045, 10.7182) radius 0.9998 from (-35.7044, 11.718) to (-36.6716, 10.9719) ccw from edge [face of Solid2 | face of Solid2]
      projected line E9 (-37.7695, 6.7862) -> (-36.6716, 10.9719) from edge [face of Solid2 | face of Solid2]
      projected arc E10 centre (-36.319, 6.4055) radius 1.4997 from (-37.7695, 6.7862) to (-36.3188, 4.9059) ccw from edge [face of Solid2 | face of Solid2]
      projected line E11 (-33.6371, 4.9059) -> (-36.3188, 4.9059) from edge [face of Solid2 | face of Solid2]
      projected arc E12 centre (-33.637, 6.6555) radius 1.7496 from (-33.6371, 4.9059) to (-31.8873, 6.6556) ccw from edge [face of Solid2 | face of Solid2]
      projected line E13 (-48.4926, -7.4437) -> (-49.8869, -7.4437) from edge [face of Solid2 | face of Solid2]
      projected curve E14 from edge [face of Solid2 | face of Solid2]
      projected line E15 (-51.798, -10.0318) -> (-50.6622, -13.7207) from edge [face of Solid2 | face of Solid2]
      projected curve E16 from edge [face of Solid2 | face of Solid2]
      projected curve E17 from edge [face of Solid2 | face of Solid2]
      projected line E18 (-49.2288, -14.7792) -> (-48.8515, -14.7792) from edge [face of Solid2 | face of Solid2]
      projected line E19 (-47.3891, -13.6117) -> (-46.5426, -9.8864) from edge [face of Solid2 | face of Solid2]
      projected curve E20 from edge [face of Solid2 | face of Solid2]
      projected line E21 (-64.0401, 11.1111) -> (-70.083, 11.1111) from edge [face of Solid2 | face of Solid2]
      projected curve E22 from edge [face of Solid2 | face of Solid2]
      projected line E23 (-61.4946, 7.5571) -> (-62.1226, 9.6789) from edge [face of Solid2 | face of Solid2]
      projected curve E24 from edge [face of Solid2 | face of Solid2]
      projected line E25 (-70.083, 5.0483) -> (-63.3121, 5.0483) from edge [face of Solid2 | face of Solid2]
      projected curve E26 from edge [face of Solid2 | face of Solid2]
      projected line E27 (-72.0827, 9.1114) -> (-72.0827, 7.048) from edge [face of Solid2 | face of Solid2]
      projected curve E28 from edge [face of Solid2 | face of Solid2]
      projected arc E29 centre (-63.414, 6.9893) radius 2.0016 from (-61.4124, 6.9896) to (-61.4946, 7.5571) ccw from edge [face of Solid2 | face of Solid2]
      projected line E30 (-61.4124, 6.948) -> (-61.4124, 6.9896) from edge [face of Solid2 | face of Solid2]
    Pocket10: profile Sketch22, direction (0, 0, 1), length 6
    Sketch23 on face of Pad2 from Sketch20.L1, origin (-77.9488, 0, 0), H (0, -1, 0), V (0, 0, 1)
      projected line E1 (5.1983, 2.65) -> (11.1983, 2.65) from edge [face of Pocket9 from Sketch21.E1 | face of Pad2 from Sketch20.L1]
      projected line E2 (5.1982, 2.65) -> (11.1983, 2.65) from edge [face of Pocket9 from Sketch21.E1 | face of Pad2 from Sketch20.L1]
      point P2 (11.1983, 2.65)
      projected arc E3 centre (11.1982, 0.15) radius 2.5 from (12.497, 2.2862) to (11.1983, 2.65) ccw from edge [face of Pocket9 from Sketch21.E2 | face of Pad2 from Sketch20.L1]
      point P4 (11.1983, 2.65)
      projected arc E4 centre (11.1982, 0.15) radius 2.5 from (13.6983, 0.15) to (12.497, 2.2862) ccw from edge [face of Pad2 from Sketch20.A14 | face of Pocket9 from Sketch21.E2]
      projected arc E5 centre (11.1982, 0.15) radius 2.5 from (12.497, -1.9862) to (13.6983, 0.15) ccw from edge [face of Pocket9 from Sketch21.E3 | face of Pad2 from Sketch20.A14]
      projected arc E6 centre (11.1982, 0.15) radius 2.5 from (11.1983, -2.35) to (12.497, -1.9862) ccw from edge [face of Pocket9 from Sketch21.E3 | face of Pad2 from Sketch20.L1]
      point P9 (11.1983, -2.35)
      projected line E7 (5.1983, -2.35) -> (11.1983, -2.35) from edge [face of Pad2 from Sketch20.L1 | face of Pocket9 from Sketch21.E4]
      projected line E8 (5.1982, -2.35) -> (11.1983, -2.35) from edge [face of Pad2 from Sketch20.L1 | face of Pocket9 from Sketch21.E4]
      point P12 (11.1983, -2.35)
      arc A1 centre (5.1982, 0.15) radius 2.5 from (5.1982, -2.35) to (5.1982, 2.65) ccw
      reference projected arc E9 centre (5.1982, 0.15) radius 2.5 from (4.1662, 2.427) to (2.8937, 1.1191) ccw from edge [face of Pocket9 from Sketch21.E7 | face of Pad2 from Sketch20.L1]
      reference projected arc E10 centre (5.1982, 0.15) radius 2.5 from (4.1662, 2.427) to (2.8937, 1.1191) ccw from edge [face of Pocket9 from Sketch21.E7 | face of Pad2 from Sketch20.L1]
      concentricity: A1 E9
      coincidence: A1 E10, P2 P4, P9 P12
    Pad3: profile Sketch23, direction (1, 0, 0), up to face of Pocket10 from Sketch22.E27
    Sketch24 on start face of Pad2, origin (0, 0, -6.85), H (1, 0, 0), V (0, -1, 0)
      projected arc E1 centre (-74.7475, 12.497) radius 3.2013 from (-74.7475, 15.6983) to (-77.9488, 12.497) ccw from edge [face of Pad2 from Sketch20.A14 | start face of Pad2]
    Pocket11: profile Sketch24, direction (0, 0, 1), length 43
  Add1: tool Body5
  Split14: SplitPlane face of Solid3
  Split15: SplitPlane face of Solid3
  Split16: SplitPlane face of Solid3
  Split17: SplitPlane face of Solid3
  Split18: SplitPlane face of Solid3
  Fillet53: radius 1.5, on edge [face of Pad2 | face of Pad2 from Sketch20.L12]; edge [face of Pad2 from Sketch20.L11 | face of Pad2]; edge [face of Solid3 | face of Pad2]; edge [face of Solid3 | face of Solid3] (x10)
  Symmetry1: ToTransfor Fillet53, Reference Plane1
